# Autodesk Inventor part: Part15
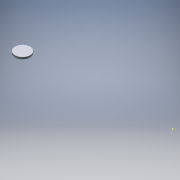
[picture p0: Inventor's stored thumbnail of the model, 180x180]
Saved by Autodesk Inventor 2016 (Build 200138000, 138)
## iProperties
Created: 2020-04
Part Number: Part15
Material: Generic
Document SubType Name: Modeling
Designer: merlin
Density: 1 g/cm^3
Appearance: Default
Author: merlin
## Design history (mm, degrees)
sketch "Sketch1"
  geometry: 1 further point
node "3D Sketch1"
sketch "Sketch2"
  geometry: C1 r 11.557 at (215.9, 14.287); 1 further point
  constraints: 1 centre point
extrude "Extrusion1" new body sketch "Sketch2" distance "d0" = 3.048; taper "d1" = 0 deg
body "Solid1"
